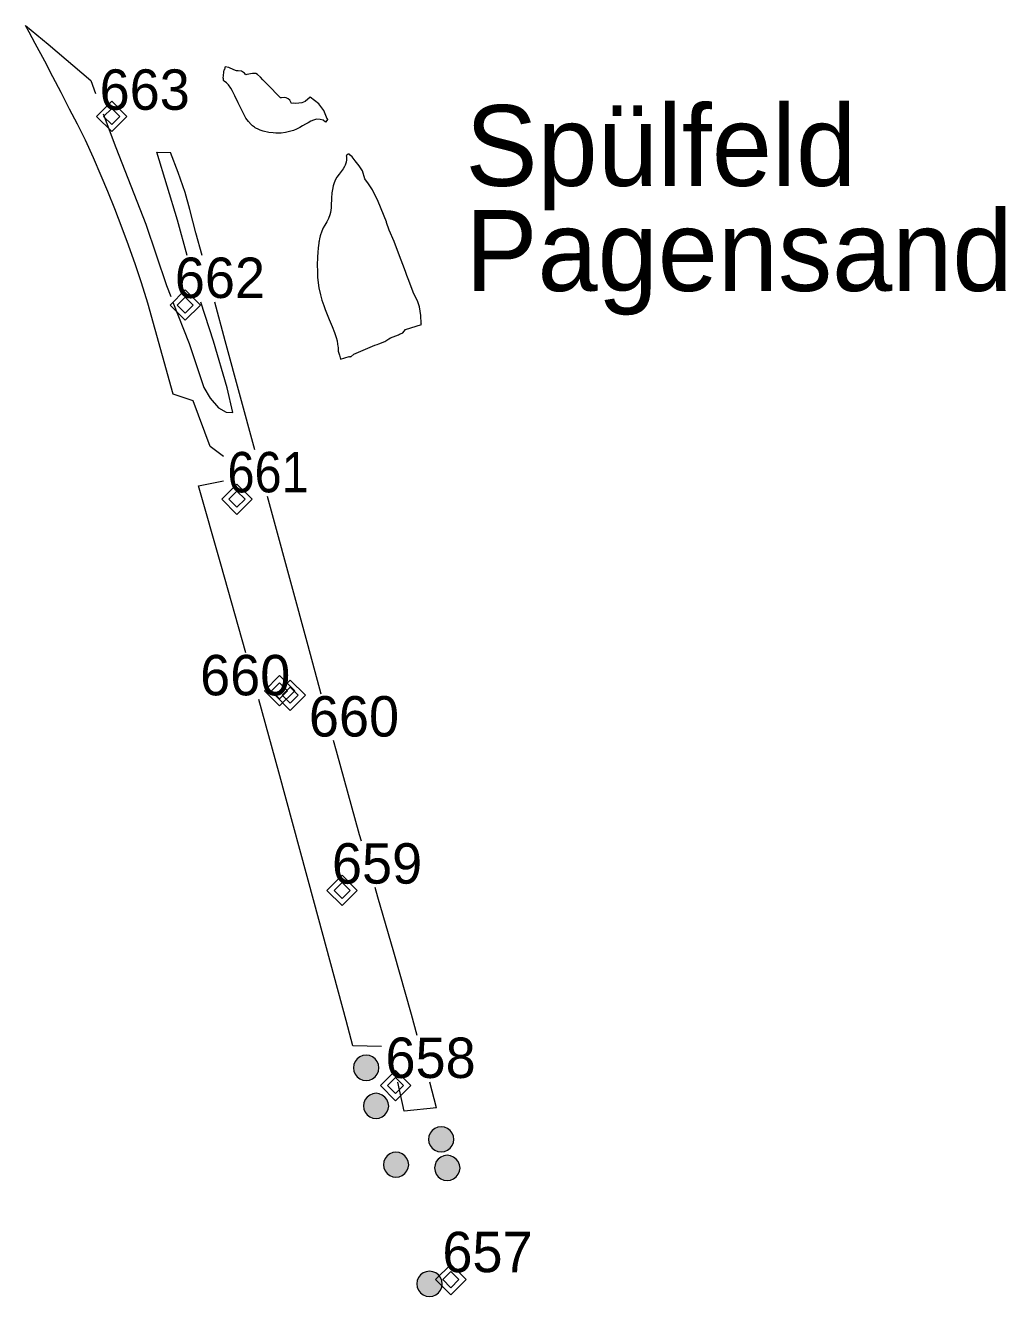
# Model space of a CAD drawing. Extents: x 3461750 to 3585707, y 5917729 to 5985917.
# Drawn here: x 3532281 to 3537130, y 5946373 to 5952666 of the extents above; entities that cross this region are included whole.
import ezdxf

# ---------------------------------------------------------------- set-up
doc = ezdxf.new("R2010")
doc.units = 0
doc.header["$LTSCALE"] = 80
for name, color, linetype, lineweight in [('13', 7, 'Continuous', 13), ('14', 7, 'Continuous', 13), ('15', 7, 'Continuous', 13), ('2', 7, 'Continuous', 13), ('3', 7, 'Continuous', 13), ('8', 7, 'Continuous', 13)]:
    doc.layers.add(name, color=color, linetype=linetype, lineweight=lineweight)

msp = doc.modelspace()

# ---------------------------------------------------------------- hatches: boundary and pattern name
at = {"layer": '3'}
for points in [[(3534030.07, 5947504.65), (3534027.14, 5947521.27), (3534020.89, 5947536.37), (3534010.95, 5947549.33), (3533997.99, 5947559.27), (3533982.89, 5947565.52), (3533966.7, 5947567.65), (3533950.5, 5947565.52), (3533935.41, 5947559.27), (3533922.45, 5947549.33), (3533912.51, 5947536.37), (3533906.26, 5947521.27), (3533904.12, 5947505.08), (3533906.26, 5947488.88), (3533912.51, 5947473.79), (3533922.45, 5947460.83), (3533935.41, 5947450.89), (3533950.5, 5947444.64), (3533966.7, 5947442.5), (3533982.89, 5947444.64), (3533997.99, 5947450.89), (3534010.95, 5947460.83), (3534020.89, 5947473.79), (3534027.14, 5947488.88)], [(3534078.75, 5947316.07), (3534075.82, 5947332.7), (3534069.57, 5947347.79), (3534059.63, 5947360.75), (3534046.67, 5947370.7), (3534031.58, 5947376.95), (3534015.38, 5947379.08), (3533999.19, 5947376.95), (3533984.09, 5947370.7), (3533971.13, 5947360.75), (3533961.19, 5947347.79), (3533954.94, 5947332.7), (3533952.81, 5947316.5), (3533954.94, 5947300.31), (3533961.19, 5947285.22), (3533971.13, 5947272.26), (3533984.09, 5947262.31), (3533999.19, 5947256.06), (3534015.38, 5947253.93), (3534031.58, 5947256.06), (3534046.67, 5947262.31), (3534059.63, 5947272.26), (3534069.57, 5947285.22), (3534075.82, 5947300.31)], [(3534401.17, 5947150.84), (3534398.24, 5947167.47), (3534391.98, 5947182.56), (3534382.04, 5947195.52), (3534369.08, 5947205.46), (3534353.99, 5947211.71), (3534337.79, 5947213.85), (3534321.6, 5947211.71), (3534306.51, 5947205.46), (3534293.55, 5947195.52), (3534283.6, 5947182.56), (3534277.35, 5947167.47), (3534275.22, 5947151.27), (3534277.35, 5947135.07), (3534283.6, 5947119.98), (3534293.55, 5947107.02), (3534306.51, 5947097.08), (3534321.6, 5947090.83), (3534337.79, 5947088.69), (3534353.99, 5947090.83), (3534369.08, 5947097.08), (3534382.04, 5947107.02), (3534391.98, 5947119.98), (3534398.24, 5947135.07)], [(3534177.63, 5947025.45), (3534174.7, 5947042.07), (3534168.45, 5947057.17), (3534158.51, 5947070.13), (3534145.55, 5947080.07), (3534130.45, 5947086.32), (3534114.26, 5947088.45), (3534098.06, 5947086.32), (3534082.97, 5947080.07), (3534070.01, 5947070.13), (3534060.07, 5947057.17), (3534053.82, 5947042.07), (3534051.68, 5947025.88), (3534053.82, 5947009.68), (3534060.07, 5946994.59), (3534070.01, 5946981.63), (3534082.97, 5946971.69), (3534098.06, 5946965.44), (3534114.26, 5946963.3), (3534130.45, 5946965.44), (3534145.55, 5946971.69), (3534158.51, 5946981.63), (3534168.45, 5946994.59), (3534174.7, 5947009.68)], [(3534431.24, 5947009.14), (3534428.31, 5947025.77), (3534422.06, 5947040.86), (3534412.12, 5947053.82), (3534399.16, 5947063.76), (3534384.07, 5947070.01), (3534367.87, 5947072.15), (3534351.68, 5947070.01), (3534336.58, 5947063.76), (3534323.62, 5947053.82), (3534313.68, 5947040.86), (3534307.43, 5947025.77), (3534305.3, 5947009.57), (3534307.43, 5946993.37), (3534313.68, 5946978.28), (3534323.62, 5946965.32), (3534336.58, 5946955.38), (3534351.68, 5946949.13), (3534367.87, 5946946.99), (3534384.07, 5946949.13), (3534399.16, 5946955.38), (3534412.12, 5946965.32), (3534422.06, 5946978.28), (3534428.31, 5946993.37)], [(3534343.45, 5946435.02), (3534340.52, 5946451.64), (3534334.27, 5946466.74), (3534324.33, 5946479.7), (3534311.37, 5946489.64), (3534296.27, 5946495.89), (3534280.08, 5946498.02), (3534263.88, 5946495.89), (3534248.79, 5946489.64), (3534235.83, 5946479.7), (3534225.89, 5946466.74), (3534219.64, 5946451.64), (3534217.5, 5946435.45), (3534219.64, 5946419.25), (3534225.89, 5946404.16), (3534235.83, 5946391.2), (3534248.79, 5946381.26), (3534263.88, 5946375.01), (3534280.08, 5946372.87), (3534296.27, 5946375.01), (3534311.37, 5946381.26), (3534324.33, 5946391.2), (3534334.27, 5946404.16), (3534340.52, 5946419.25)]]:
    msp.add_hatch(color=256, dxfattribs=at).paths.add_polyline_path(points)

# ---------------------------------------------------------------- linework, layer by layer
at = {"layer": '13'}
for points in [[(3533538.17, 5949446.68), (3533463.08, 5949371.59), (3533538.17, 5949296.5), (3533613.26, 5949371.59)], [(3533538.17, 5949411.29), (3533498.47, 5949371.59), (3533538.17, 5949331.9), (3533577.86, 5949371.59)]]:
    msp.add_lwpolyline(points, close=True, dxfattribs=at)
at = {"layer": '14'}
for points in [[(3533590.8, 5949424.71), (3533515.71, 5949349.62), (3533590.8, 5949274.53), (3533665.89, 5949349.62)], [(3533590.8, 5949389.31), (3533551.11, 5949349.62), (3533590.8, 5949309.93), (3533630.5, 5949349.62)]]:
    msp.add_lwpolyline(points, close=True, dxfattribs=at)
at = {"layer": '15'}
for points in [[(3532707.7, 5952290.24), (3532632.61, 5952215.15), (3532707.7, 5952140.06), (3532782.79, 5952215.15)], [(3532707.7, 5952254.84), (3532668.01, 5952215.15), (3532707.7, 5952175.46), (3532747.39, 5952215.15)], [(3533071.52, 5951356.06), (3532996.43, 5951280.97), (3533071.52, 5951205.88), (3533146.61, 5951280.97)], [(3533071.52, 5951320.66), (3533031.82, 5951280.97), (3533071.52, 5951241.28), (3533111.21, 5951280.97)], [(3533327.67, 5950395.12), (3533252.58, 5950320.03), (3533327.67, 5950244.94), (3533402.76, 5950320.03)], [(3533327.67, 5950359.72), (3533287.98, 5950320.03), (3533327.67, 5950280.34), (3533367.36, 5950320.03)], [(3533847.3, 5948458.31), (3533772.21, 5948383.22), (3533847.3, 5948308.12), (3533922.39, 5948383.22)], [(3533847.3, 5948422.91), (3533807.61, 5948383.22), (3533847.3, 5948343.52), (3533886.99, 5948383.22)], [(3534112.29, 5947492.78), (3534037.2, 5947417.69), (3534112.29, 5947342.6), (3534187.38, 5947417.69)], [(3534112.29, 5947457.38), (3534072.6, 5947417.69), (3534112.29, 5947378), (3534151.98, 5947417.69)], [(3534385.58, 5946531.74), (3534310.49, 5946456.65), (3534385.58, 5946381.56), (3534460.67, 5946456.65)], [(3534385.58, 5946496.35), (3534345.89, 5946456.65), (3534385.58, 5946416.96), (3534425.27, 5946456.65)]]:
    msp.add_lwpolyline(points, close=True, dxfattribs=at)
at = {"layer": '2'}
for p, q in [((3534042.2, 5947610.99), (3533900.59, 5947614.75)), ((3534314.84, 5947307.52), (3534281.16, 5947435))]:
    msp.add_line(p, q, dxfattribs=at)
for points in [[(3533011.72, 5950839.36), (3532958.79, 5951030.66), (3532886.72, 5951290.23), (3532855.32, 5951391.8), (3532826.22, 5951480.18), (3532790.33, 5951577.25), (3532759.86, 5951661.72), (3532723.44, 5951757.23), (3532687.99, 5951843.55), (3532656.01, 5951921.78), (3532617.38, 5952010.64), (3532577.49, 5952097.85), (3532538.82, 5952177.05), (3532498.97, 5952251.37), (3532457.37, 5952334.38), (3532416.46, 5952411.91), (3532376.27, 5952488.09), (3532330.03, 5952576.56), (3532299.32, 5952632.62), (3532281.1, 5952665.62)], [(3532281.1, 5952665.62), (3532393.41, 5952573.14), (3532603.81, 5952392.97), (3532628, 5952328.45)], [(3532665.7, 5952227.9), (3532728.42, 5952060.64), (3532876.61, 5951681.93), (3532979.05, 5951378.32), (3533000.2, 5951323.86)], [(3533081.7, 5951526.3), (3533033.89, 5951702.15), (3532930.71, 5952038.96), (3532998.29, 5952036.13)], [(3533155.57, 5951526.3), (3533124.85, 5951639.55), (3533094.14, 5951754.88), (3533070.8, 5951839.16), (3533036.38, 5951937.01), (3532998.29, 5952036.13)], [(3533010.9, 5951296.3), (3533090.38, 5951091.6), (3533163.92, 5950872.85), (3533195.21, 5950820.7), (3533235.6, 5950772.85), (3533274.07, 5950751.37), (3533306.93, 5950749.51), (3533279.74, 5950871.48), (3533210.89, 5951102.34), (3533149.14, 5951296.3)], [(3533416.53, 5950564.1), (3533269.97, 5951104.49), (3533217.95, 5951296.3)], [(3533260.7, 5950531.57), (3533195.61, 5950581.35), (3533110.11, 5950806.64), (3533011.72, 5950839.36)], [(3533371.86, 5949559.2), (3533247.51, 5949998.83), (3533137.21, 5950386.52), (3533260.7, 5950411.69)], [(3533744.07, 5949355.3), (3533680.03, 5949593.55), (3533508.4, 5950225.39), (3533478.91, 5950334.1)], [(3533900.59, 5947614.75), (3533867.19, 5947738.77), (3533710.74, 5948317.97), (3533535.21, 5948968.65), (3533435.55, 5949329.2)], [(3533943.36, 5948627.2), (3533934.38, 5948658.01), (3533819.97, 5949072.95), (3533805.9, 5949125.3)], [(3534218.82, 5947665), (3534190.72, 5947768.46), (3534103.22, 5948077.25), (3534024.32, 5948349.61), (3534010.44, 5948397.2)], [(3534314.84, 5947307.52), (3534154.93, 5947291.02), (3534123.14, 5947435)]]:
    msp.add_lwpolyline(points, dxfattribs=at)
at = {"layer": '3'}
for points in [[(3534030.07, 5947504.65), (3534027.14, 5947521.27), (3534020.89, 5947536.37), (3534010.95, 5947549.33), (3533997.99, 5947559.27), (3533982.89, 5947565.52), (3533966.7, 5947567.65), (3533950.5, 5947565.52), (3533935.41, 5947559.27), (3533922.45, 5947549.33), (3533912.51, 5947536.37), (3533906.26, 5947521.27), (3533904.12, 5947505.08), (3533906.26, 5947488.88), (3533912.51, 5947473.79), (3533922.45, 5947460.83), (3533935.41, 5947450.89), (3533950.5, 5947444.64), (3533966.7, 5947442.5), (3533982.89, 5947444.64), (3533997.99, 5947450.89), (3534010.95, 5947460.83), (3534020.89, 5947473.79), (3534027.14, 5947488.88)], [(3534078.75, 5947316.07), (3534075.82, 5947332.7), (3534069.57, 5947347.79), (3534059.63, 5947360.75), (3534046.67, 5947370.7), (3534031.58, 5947376.95), (3534015.38, 5947379.08), (3533999.19, 5947376.95), (3533984.09, 5947370.7), (3533971.13, 5947360.75), (3533961.19, 5947347.79), (3533954.94, 5947332.7), (3533952.81, 5947316.5), (3533954.94, 5947300.31), (3533961.19, 5947285.22), (3533971.13, 5947272.26), (3533984.09, 5947262.31), (3533999.19, 5947256.06), (3534015.38, 5947253.93), (3534031.58, 5947256.06), (3534046.67, 5947262.31), (3534059.63, 5947272.26), (3534069.57, 5947285.22), (3534075.82, 5947300.31)], [(3534401.17, 5947150.84), (3534398.24, 5947167.47), (3534391.98, 5947182.56), (3534382.04, 5947195.52), (3534369.08, 5947205.46), (3534353.99, 5947211.71), (3534337.79, 5947213.85), (3534321.6, 5947211.71), (3534306.51, 5947205.46), (3534293.55, 5947195.52), (3534283.6, 5947182.56), (3534277.35, 5947167.47), (3534275.22, 5947151.27), (3534277.35, 5947135.07), (3534283.6, 5947119.98), (3534293.55, 5947107.02), (3534306.51, 5947097.08), (3534321.6, 5947090.83), (3534337.79, 5947088.69), (3534353.99, 5947090.83), (3534369.08, 5947097.08), (3534382.04, 5947107.02), (3534391.98, 5947119.98), (3534398.24, 5947135.07)], [(3534177.63, 5947025.45), (3534174.7, 5947042.07), (3534168.45, 5947057.17), (3534158.51, 5947070.13), (3534145.55, 5947080.07), (3534130.45, 5947086.32), (3534114.26, 5947088.45), (3534098.06, 5947086.32), (3534082.97, 5947080.07), (3534070.01, 5947070.13), (3534060.07, 5947057.17), (3534053.82, 5947042.07), (3534051.68, 5947025.88), (3534053.82, 5947009.68), (3534060.07, 5946994.59), (3534070.01, 5946981.63), (3534082.97, 5946971.69), (3534098.06, 5946965.44), (3534114.26, 5946963.3), (3534130.45, 5946965.44), (3534145.55, 5946971.69), (3534158.51, 5946981.63), (3534168.45, 5946994.59), (3534174.7, 5947009.68)], [(3534431.24, 5947009.14), (3534428.31, 5947025.77), (3534422.06, 5947040.86), (3534412.12, 5947053.82), (3534399.16, 5947063.76), (3534384.07, 5947070.01), (3534367.87, 5947072.15), (3534351.68, 5947070.01), (3534336.58, 5947063.76), (3534323.62, 5947053.82), (3534313.68, 5947040.86), (3534307.43, 5947025.77), (3534305.3, 5947009.57), (3534307.43, 5946993.37), (3534313.68, 5946978.28), (3534323.62, 5946965.32), (3534336.58, 5946955.38), (3534351.68, 5946949.13), (3534367.87, 5946946.99), (3534384.07, 5946949.13), (3534399.16, 5946955.38), (3534412.12, 5946965.32), (3534422.06, 5946978.28), (3534428.31, 5946993.37)], [(3534343.45, 5946435.02), (3534340.52, 5946451.64), (3534334.27, 5946466.74), (3534324.33, 5946479.7), (3534311.37, 5946489.64), (3534296.27, 5946495.89), (3534280.08, 5946498.02), (3534263.88, 5946495.89), (3534248.79, 5946489.64), (3534235.83, 5946479.7), (3534225.89, 5946466.74), (3534219.64, 5946451.64), (3534217.5, 5946435.45), (3534219.64, 5946419.25), (3534225.89, 5946404.16), (3534235.83, 5946391.2), (3534248.79, 5946381.26), (3534263.88, 5946375.01), (3534280.08, 5946372.87), (3534296.27, 5946375.01), (3534311.37, 5946381.26), (3534324.33, 5946391.2), (3534334.27, 5946404.16), (3534340.52, 5946419.25)]]:
    msp.add_lwpolyline(points, close=True, dxfattribs=at)
at = {"layer": '8'}
for p, q in [((3533264.26, 5952445.21), (3533266.02, 5952447.27)), ((3533267.92, 5952455.08), (3533266.02, 5952447.27)), ((3533776.27, 5952201.17), (3533774.07, 5952204)), ((3533413.62, 5952161.91), (3533404.54, 5952169.14)), ((3533446.97, 5952145.7), (3533442.92, 5952147.17)), ((3533867.72, 5951989.26), (3533867.48, 5951988.09)), ((3533796.58, 5951836.62), (3533796.53, 5951836.62)), ((3534130.96, 5951136.72), (3534144.14, 5951142.09)), ((3534020.75, 5951086.43), (3534029.2, 5951089.75)), ((3533860.89, 5951020.51), (3533881.84, 5951027.25))]:
    msp.add_line(p, q, dxfattribs=at)
for points in [[(3533260.16, 5952403.71), (3533260.06, 5952404.69), (3533260.79, 5952418.26), (3533262.16, 5952434.18), (3533264.26, 5952445.21)], [(3533774.07, 5952204), (3533757.81, 5952243.75), (3533732.03, 5952277.54), (3533690.28, 5952310.64), (3533665.09, 5952288.96), (3533649.07, 5952283.2), (3533618.16, 5952279.2), (3533605.62, 5952280.37), (3533597.61, 5952279.2), (3533589.31, 5952294.82), (3533580.76, 5952302.93), (3533570.75, 5952307.23), (3533561.67, 5952308.4), (3533547.12, 5952307.91), (3533542.63, 5952307.71), (3533476.32, 5952375.59), (3533455.86, 5952395.61), (3533443.21, 5952409.28), (3533428.66, 5952422.56), (3533420.07, 5952427.05), (3533404.79, 5952427.05), (3533377.15, 5952422.07), (3533371.44, 5952421.58), (3533364.06, 5952428.52), (3533349.51, 5952439.65), (3533333.79, 5952441.11), (3533324.95, 5952440.92), (3533312.11, 5952446.19), (3533287.79, 5952458.11), (3533269.43, 5952461.13), (3533267.92, 5952455.08)], [(3533404.54, 5952169.14), (3533397.51, 5952174.8), (3533384.03, 5952189.55), (3533371.58, 5952207.23), (3533357.81, 5952233.2), (3533345.17, 5952258.79), (3533333.5, 5952282.62), (3533316.16, 5952317.19), (3533303.52, 5952343.16), (3533297.07, 5952355.27), (3533285.4, 5952372.07), (3533275.68, 5952381.54), (3533264.75, 5952390.14), (3533261.23, 5952392.58), (3533260.16, 5952403.71)], [(3533776.27, 5952201.17), (3533765.97, 5952187.21), (3533753.42, 5952196.58), (3533738.38, 5952200.68), (3533720.46, 5952200.98), (3533706.3, 5952196.88), (3533693.46, 5952191.31), (3533679, 5952183.4), (3533665.87, 5952175.98), (3533652.05, 5952168.16), (3533638.43, 5952160.55), (3533622.56, 5952152.64), (3533606.4, 5952145.51), (3533587.84, 5952139.75), (3533567.53, 5952135.25), (3533546.97, 5952132.52), (3533527.2, 5952132.23)], [(3533442.92, 5952147.17), (3533435.21, 5952149.9), (3533417.09, 5952159.08), (3533413.62, 5952161.91)], [(3533505.86, 5952133.3), (3533485.99, 5952135.25), (3533456.4, 5952142.48), (3533446.97, 5952145.7)], [(3533527.2, 5952132.23), (3533519.63, 5952132.03), (3533505.86, 5952133.3)], [(3533869.78, 5952003.91), (3533869.87, 5951999.9), (3533867.72, 5951989.26)], [(3533881.45, 5952028.81), (3533877.98, 5952027.64), (3533871.63, 5952023.93), (3533868.31, 5952020.21), (3533868.9, 5952015.92)], [(3533868.9, 5952015.92), (3533869.53, 5952010.55), (3533869.78, 5952003.91)], [(3533886.82, 5952023.54), (3533883.25, 5952029.49), (3533881.45, 5952028.81)], [(3534067.87, 5951690.53), (3534066.89, 5951693.26), (3534025.34, 5951793.26), (3533997.61, 5951852.15), (3533978.12, 5951881.15), (3533960.79, 5951906.64), (3533948.68, 5951945.21), (3533932.23, 5951970.8), (3533911.87, 5951995.41), (3533898.05, 5952014.94), (3533886.82, 5952023.54)], [(3533862.26, 5951973.63), (3533859.47, 5951967.09), (3533853.17, 5951954.98), (3533843.16, 5951942.97), (3533832.32, 5951929), (3533821.83, 5951914.55), (3533815.33, 5951902.34), (3533808.4, 5951886.23), (3533803.47, 5951871.29), (3533799.41, 5951853.71), (3533796.58, 5951836.62), (3533796.53, 5951836.62), (3533796.48, 5951836.13), (3533795.26, 5951810.84), (3533794.43, 5951795.21), (3533793.99, 5951786.91), (3533793.46, 5951762.6), (3533790.23, 5951739.06), (3533787.3, 5951727.25), (3533781.1, 5951710.45), (3533772.27, 5951692.87), (3533762.11, 5951676.56), (3533754, 5951663.48), (3533747.12, 5951647.17), (3533739.01, 5951623.93), (3533735.6, 5951609.08), (3533734.08, 5951598.93)], [(3533867.48, 5951988.09), (3533866.7, 5951984.08), (3533862.26, 5951973.63)], [(3533796.53, 5951836.62), (3533796.53, 5951836.72), (3533796.58, 5951836.62), (3533796.53, 5951836.72), (3533796.58, 5951836.52), (3533796.58, 5951836.62)], [(3533796.53, 5951836.62), (3533796.58, 5951836.62), (3533796.58, 5951836.52)], [(3534160.79, 5951446.97), (3534126.22, 5951537.79), (3534104.98, 5951595.31), (3534081.2, 5951652.54), (3534067.87, 5951690.53)], [(3533728.91, 5951562.11), (3533727.29, 5951544.04), (3533725.44, 5951516.21), (3533724.51, 5951480.86), (3533725.39, 5951447.95), (3533726.32, 5951419.82), (3533729.3, 5951391.6), (3533729.44, 5951390.62), (3533733.25, 5951366.99), (3533739.99, 5951332.13), (3533747.71, 5951305.27), (3533757.13, 5951279.2), (3533764.6, 5951259.47), (3533771.14, 5951242.19), (3533784.03, 5951210.55), (3533798.78, 5951174.61), (3533809.91, 5951144.82), (3533818.46, 5951119.92), (3533822.46, 5951104.1), (3533825.49, 5951087.11), (3533826.81, 5951078.52)], [(3533733.15, 5951592.48), (3533732.32, 5951587.01), (3533729, 5951563.77), (3533728.91, 5951562.11)], [(3533734.08, 5951598.93), (3533733.84, 5951597.07), (3533733.15, 5951592.48)], [(3534239.4, 5951190.43), (3534237.55, 5951229), (3534230.18, 5951272.27), (3534220.65, 5951302.64), (3534202, 5951337.3), (3534174.71, 5951410.45), (3534168.41, 5951427.05), (3534160.79, 5951446.97)], [(3534144.14, 5951142.09), (3534147.9, 5951143.65), (3534161.33, 5951159.67), (3534239.7, 5951185.25), (3534239.4, 5951190.43)], [(3534078.42, 5951113.77), (3534086.87, 5951119.04), (3534125.83, 5951134.57), (3534130.96, 5951136.72)], [(3533826.81, 5951078.52), (3533827.83, 5951071.39), (3533828.71, 5951058.2), (3533829, 5951053.03), (3533834.67, 5951032.52), (3533839.84, 5951013.77), (3533860.89, 5951020.51)], [(3533881.84, 5951027.25), (3533882.28, 5951022.85), (3533884.13, 5951026.66), (3533886.87, 5951026.37), (3533890.77, 5951024.8), (3533905.86, 5951037.6), (3534009.08, 5951081.93), (3534020.75, 5951086.43)], [(3534029.2, 5951089.75), (3534058.69, 5951101.27), (3534078.42, 5951113.77)]]:
    msp.add_lwpolyline(points, dxfattribs=at)

# ---------------------------------------------------------------- texts
at = {"layer": '13'}
msp.add_text('660', height=200, dxfattribs=at).set_placement((3533145.1, 5949349.2))
at = {"layer": '14'}
msp.add_text('660', height=200, dxfattribs=at).set_placement((3533683.4, 5949145.3))
at = {"layer": '15'}
for s, p in [('663', (3532648, 5952247.9)), ('662', (3533020.2, 5951316.3)), ('659', (3533797.5, 5948417.2)), ('658', (3534062.2, 5947455)), ('657', (3534343.8, 5946493.6))]:
    msp.add_text(s, height=200, dxfattribs=at).set_placement(p)
at = {"layer": '15', "width": 0.9}
msp.add_text('661', height=200, dxfattribs=at).set_placement((3533280.7, 5950354.1))
at = {"layer": '8'}
for s, p in [('Spülfeld', (3534457.7, 5951871.1)), ('Pagensand', (3534457.7, 5951351.1))]:
    msp.add_text(s, height=400, dxfattribs=at).set_placement(p)

doc.saveas('drawing.dxf')
